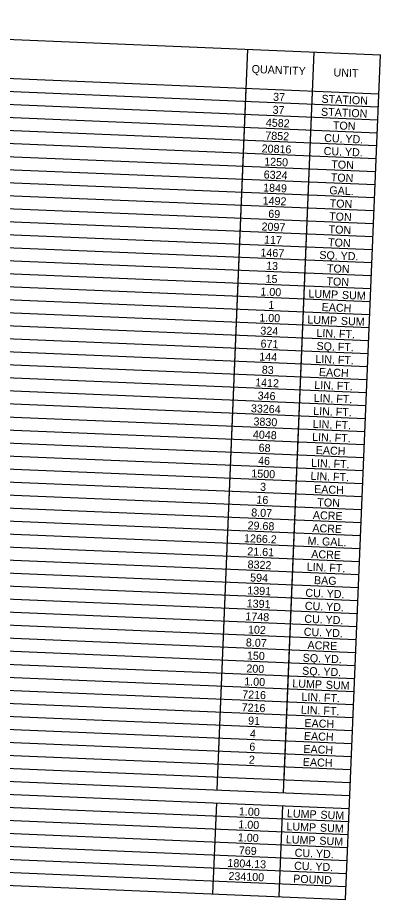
# Model space of a CAD drawing. Extents: x 1164179 to 1171425, y 1655958 to 1657208.
# Drawn here: x 1170350 to 1170622, y 1656114 to 1656775 of the extents above; entities that cross this region are included whole.
import ezdxf

# ---------------------------------------------------------------- set-up
doc = ezdxf.new("R2010")
doc.units = 0
doc.layers.add('Default', color=7, linetype='Continuous')

msp = doc.modelspace()

# ---------------------------------------------------------------- linework, layer by layer
at = {"layer": 'Default'}
for p, q in [((1169950.5, 1656775.14), (1170622.19, 1656747.35)), ((1170499.85, 1656196.19), (1170522.82, 1656751.46)), ((1169949.29, 1656745.91), (1170620.98, 1656718.13)), ((1170549.53, 1656194.13), (1170572.5, 1656749.41)), ((1170549.94, 1656203.88), (1170572.5, 1656749.41)), ((1170595.99, 1656114.14), (1170622.19, 1656747.35)), ((1169948.89, 1656736.17), (1170620.57, 1656708.39)), ((1169948.48, 1656726.43), (1170620.17, 1656698.64)), ((1170499.85, 1656196.19), (1170521.61, 1656722.24)), ((1169948.08, 1656716.69), (1170619.77, 1656688.9)), ((1169947.68, 1656706.95), (1170619.36, 1656679.16)), ((1169947.27, 1656697.21), (1170618.96, 1656669.42)), ((1169946.87, 1656687.46), (1170618.56, 1656659.68)), ((1169946.47, 1656677.72), (1170618.16, 1656649.94)), ((1169946.06, 1656667.98), (1170617.75, 1656640.19)), ((1169945.66, 1656658.24), (1170617.35, 1656630.45)), ((1169945.26, 1656648.5), (1170616.95, 1656620.71)), ((1169944.86, 1656638.76), (1170616.54, 1656610.97)), ((1169944.45, 1656629.01), (1170616.14, 1656601.23)), ((1169944.05, 1656619.27), (1170615.74, 1656591.49)), ((1169943.65, 1656609.53), (1170615.33, 1656581.74)), ((1169943.24, 1656599.79), (1170614.93, 1656572)), ((1169942.84, 1656590.05), (1170614.53, 1656562.26)), ((1169942.44, 1656580.31), (1170614.13, 1656552.52)), ((1169942.03, 1656570.56), (1170613.72, 1656542.78)), ((1169941.63, 1656560.82), (1170613.32, 1656533.04)), ((1169941.23, 1656551.08), (1170612.92, 1656523.29)), ((1169940.83, 1656541.34), (1170612.51, 1656513.55)), ((1169940.42, 1656531.6), (1170612.11, 1656503.81)), ((1169940.02, 1656521.86), (1170611.71, 1656494.07)), ((1169939.62, 1656512.11), (1170611.3, 1656484.33)), ((1169939.21, 1656502.37), (1170610.9, 1656474.59)), ((1169938.81, 1656492.63), (1170610.5, 1656464.84)), ((1169938.41, 1656482.89), (1170610.1, 1656455.1)), ((1169938, 1656473.15), (1170609.69, 1656445.36)), ((1169937.6, 1656463.41), (1170609.29, 1656435.62)), ((1169937.2, 1656453.66), (1170608.89, 1656425.88)), ((1169936.8, 1656443.92), (1170608.48, 1656416.14)), ((1169936.39, 1656434.18), (1170608.08, 1656406.39)), ((1169935.99, 1656424.44), (1170607.68, 1656396.65)), ((1169935.59, 1656414.7), (1170607.27, 1656386.91)), ((1169935.18, 1656404.96), (1170606.87, 1656377.17)), ((1169934.78, 1656395.21), (1170606.47, 1656367.43)), ((1169934.38, 1656385.47), (1170606.07, 1656357.69)), ((1169933.97, 1656375.73), (1170605.66, 1656347.94)), ((1169933.57, 1656365.99), (1170605.26, 1656338.2)), ((1169933.17, 1656356.25), (1170604.86, 1656328.46)), ((1169932.77, 1656346.51), (1170604.45, 1656318.72)), ((1169932.36, 1656336.76), (1170604.05, 1656308.98)), ((1169931.96, 1656327.02), (1170603.65, 1656299.24)), ((1169931.56, 1656317.28), (1170603.24, 1656289.49)), ((1169931.15, 1656307.54), (1170602.84, 1656279.75)), ((1169930.75, 1656297.8), (1170602.44, 1656270.01)), ((1169930.35, 1656288.06), (1170602.04, 1656260.27)), ((1169929.94, 1656278.31), (1170601.63, 1656250.53)), ((1169929.54, 1656268.57), (1170601.23, 1656240.79)), ((1169929.14, 1656258.83), (1170600.83, 1656231.04)), ((1169928.74, 1656249.09), (1170600.42, 1656221.3)), ((1169928.33, 1656239.35), (1170600.02, 1656211.56)), ((1169927.93, 1656229.61), (1170599.62, 1656201.82)), ((1169927.53, 1656219.86), (1170599.21, 1656192.08)), ((1169927.12, 1656210.12), (1170598.81, 1656182.34)), ((1169926.72, 1656200.38), (1170598.41, 1656172.59)), ((1169926.32, 1656190.64), (1170598.01, 1656162.85)), ((1170496.63, 1656118.26), (1170499.45, 1656186.45)), ((1170496.63, 1656118.26), (1170499.45, 1656186.45)), ((1170546.31, 1656116.2), (1170549.13, 1656184.39)), ((1170546.31, 1656116.2), (1170549.13, 1656184.39)), ((1169925.91, 1656180.9), (1170597.6, 1656153.11)), ((1169925.51, 1656171.16), (1170597.2, 1656143.37)), ((1169925.11, 1656161.41), (1170596.8, 1656133.63)), ((1169924.71, 1656151.67), (1170596.39, 1656123.89)), ((1169924.3, 1656141.93), (1170595.99, 1656114.14))]:
    msp.add_line(p, q, dxfattribs=at)

# ---------------------------------------------------------------- texts
for s, p in [('QUANTITY', (1170525.52, 1656733.71)), ('UNIT', (1170586.93, 1656731.17)), ('37', (1170541.63, 1656712.85)), ('STATION', (1170577.97, 1656711.35)), ('37', (1170541.23, 1656703.11)), ('STATION', (1170577.57, 1656701.61)), ('4582', (1170536.2, 1656693.56)), ('TON', (1170586.48, 1656691.48)), ('7852', (1170535.8, 1656683.82)), ('CU.', (1170579.95, 1656681.99)), (' YD.', (1170593.64, 1656681.43)), ('20816', (1170533.04, 1656674.18)), ('CU.', (1170579.54, 1656672.25)), (' YD.', (1170593.24, 1656671.69)), ('1250', (1170534.97, 1656664.34)), ('TON', (1170585.27, 1656662.26)), ('6324', (1170534.57, 1656654.6)), ('TON', (1170584.87, 1656652.51)), ('1849', (1170534.15, 1656644.85)), ('GAL.', (1170583.78, 1656642.8)), ('1492', (1170533.78, 1656635.11)), ('TON', (1170584.06, 1656633.03)), ('69', (1170538, 1656625.18)), ('TON', (1170583.66, 1656623.29)), ('2097', (1170532.95, 1656615.63)), ('TON', (1170583.25, 1656613.55)), ('117', (1170534.87, 1656605.79)), ('TON', (1170582.85, 1656603.81)), ('1467', (1170532.14, 1656596.15)), ('SQ.', (1170576.32, 1656594.32)), (' YD.', (1170590.02, 1656593.75)), ('13', (1170536.39, 1656586.21)), ('TON', (1170582.04, 1656584.32)), ('15', (1170535.97, 1656576.47)), ('TON', (1170581.64, 1656574.58)), ('1.00', (1170532.11, 1656566.87)), ('LUMP', (1170568.13, 1656565.38)), (' SUM', (1170591.03, 1656564.43)), ('1', (1170538.09, 1656556.87)), ('EACH', (1170578.03, 1656555.21)), ('1.00', (1170531.3, 1656547.39)), ('LUMP', (1170567.32, 1656545.9)), (' SUM', (1170590.23, 1656544.95)), ('324', (1170532.06, 1656537.6)), ('LIN.', (1170574.14, 1656535.86)), (' FT.', (1170588.76, 1656535.25)), ('671', (1170532.23, 1656527.83)), ('SQ.', (1170574.2, 1656526.1)), (' FT.', (1170587.9, 1656525.53)), ('144', (1170531.26, 1656518.12)), ('LIN.', (1170573.33, 1656516.38)), (' FT.', (1170587.96, 1656515.77)), ('83', (1170533.17, 1656508.28)), ('EACH', (1170576.02, 1656506.51)), ('1412', (1170528.14, 1656498.73)), ('LIN.', (1170572.53, 1656496.89)), (' FT.', (1170587.15, 1656496.29)), ('346', (1170530.04, 1656488.89)), ('LIN.', (1170572.12, 1656487.15)), (' FT.', (1170586.75, 1656486.55)), ('33264', (1170524.99, 1656479.34)), ('LIN.', (1170571.72, 1656477.41)), (' FT.', (1170586.35, 1656476.8)), ('3830', (1170526.91, 1656469.5)), ('LIN.', (1170571.32, 1656467.67)), (' FT.', (1170585.94, 1656467.06)), ('4048', (1170526.49, 1656459.76)), ('LIN.', (1170570.91, 1656457.93)), (' FT.', (1170585.54, 1656457.32)), ('68', (1170530.75, 1656449.83)), ('EACH', (1170573.6, 1656448.06)), ('46', (1170530.35, 1656440.09)), ('LIN.', (1170570.11, 1656438.44)), (' FT.', (1170584.73, 1656437.84)), ('1500', (1170525.3, 1656430.54)), ('LIN.', (1170569.7, 1656428.7)), (' FT.', (1170584.33, 1656428.1)), ('3', (1170531.87, 1656420.51)), ('EACH', (1170572.39, 1656418.83)), ('16', (1170529.14, 1656410.86)), ('TON', (1170574.79, 1656408.97)), ('8.07', (1170525.25, 1656401.26)), ('ACRE', (1170571.47, 1656399.35)), ('29.68', (1170522.51, 1656391.62)), ('ACRE', (1170571.07, 1656389.61)), ('1266.2', (1170519.82, 1656381.97)), ('M.', (1170567.45, 1656380)), (' GAL.', (1170576.03, 1656379.65)), ('21.61', (1170522.29, 1656372.11)), ('ACRE', (1170570.26, 1656370.13)), ('8322', (1170522.5, 1656362.34)), ('LIN.', (1170566.88, 1656360.51)), (' FT.', (1170581.51, 1656359.9)), ('594', (1170524.41, 1656352.51)), ('BAG', (1170572.29, 1656350.53)), ('1391', (1170522.24, 1656342.84)), ('CU.', (1170565.84, 1656341.03)), (' YD.', (1170579.54, 1656340.47)), ('1391', (1170521.84, 1656333.1)), ('CU.', (1170565.44, 1656331.29)), (' YD.', (1170579.13, 1656330.73)), ('1748', (1170520.85, 1656323.38)), ('CU.', (1170565.04, 1656321.55)), (' YD.', (1170578.73, 1656320.99)), ('102', (1170522.81, 1656313.54)), ('CU.', (1170564.63, 1656311.81)), (' YD.', (1170578.33, 1656311.24)), ('8.07', (1170521.22, 1656303.85)), ('ACRE', (1170567.44, 1656301.94)), ('150', (1170521.99, 1656294.06)), ('SQ.', (1170563.82, 1656292.33)), (' YD.', (1170577.52, 1656291.76)), ('200', (1170521.58, 1656284.32)), ('SQ.', (1170563.42, 1656282.58)), (' YD.', (1170577.12, 1656282.02)), ('1.00', (1170520.02, 1656274.62)), ('LUMP', (1170556.04, 1656273.13)), (' SUM', (1170578.94, 1656272.18)), ('7216', (1170518.44, 1656264.93)), ('LIN.', (1170562.85, 1656263.09)), (' FT.', (1170577.48, 1656262.49)), ('7216', (1170518.04, 1656255.19)), ('LIN.', (1170562.45, 1656253.35)), (' FT.', (1170577.08, 1656252.75)), ('91', (1170522.87, 1656245.23)), ('EACH', (1170565.14, 1656243.48)), ('4', (1170524.23, 1656235.41)), ('EACH', (1170564.74, 1656233.74)), ('6', (1170523.81, 1656225.67)), ('EACH', (1170564.33, 1656224)), ('2', (1170523.44, 1656215.93)), ('EACH', (1170563.93, 1656214.26)), ('1.00', (1170515.99, 1656177.21)), ('LUMP', (1170552.01, 1656175.72)), (' SUM', (1170574.91, 1656174.77)), ('1.00', (1170515.59, 1656167.46)), ('LUMP', (1170551.61, 1656165.97)), (' SUM', (1170574.51, 1656165.03)), ('1.00', (1170515.18, 1656157.72)), ('LUMP', (1170551.2, 1656156.23)), (' SUM', (1170574.11, 1656155.28)), ('769', (1170515.93, 1656147.93)), ('CU.', (1170557.78, 1656146.2)), (' YD.', (1170571.48, 1656145.64)), ('1804.13', (1170507.38, 1656138.53)), ('CU.', (1170557.38, 1656136.46)), (' YD.', (1170571.07, 1656135.89)), ('234100', (1170508.15, 1656128.74)), ('POUND', (1170556.7, 1656126.73))]:
    msp.add_text(s, height=6, rotation=357.63112, dxfattribs=at).set_placement(p)

doc.saveas('drawing.dxf')
